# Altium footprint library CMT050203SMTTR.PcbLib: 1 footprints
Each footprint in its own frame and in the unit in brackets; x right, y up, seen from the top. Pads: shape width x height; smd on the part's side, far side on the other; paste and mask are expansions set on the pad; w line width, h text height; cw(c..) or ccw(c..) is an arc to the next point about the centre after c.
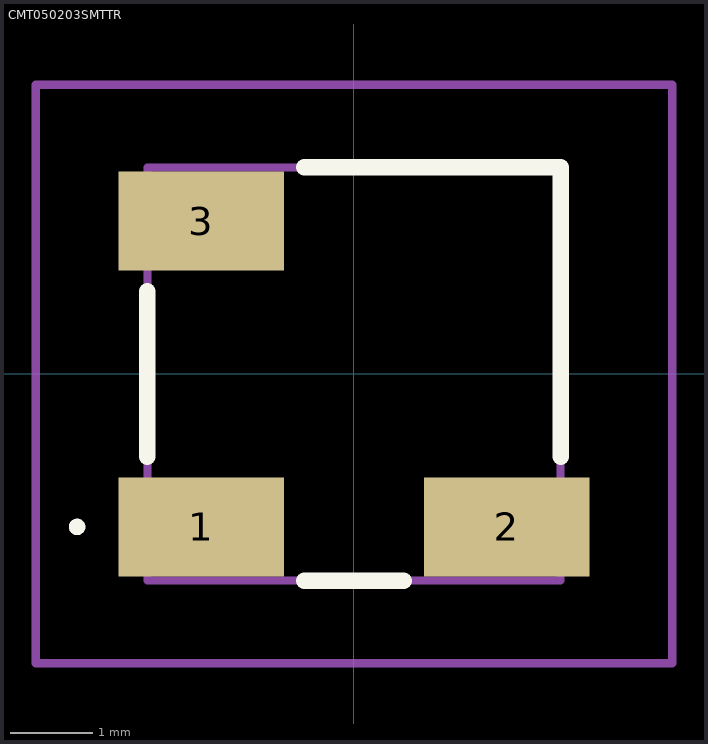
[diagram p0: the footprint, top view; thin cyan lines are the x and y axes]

## CMT050203SMTTR [mm]
pads (3):
  rect 2x1.2 smd: 1(-1.85,-1.85) 2(1.85,-1.85) 3(-1.85,1.85)
Top Overlay:
  lines w0.1: -3.4,-1.85 -3.4,-1.85 ; -3.4,-1.85 ccw(c-3.35,-1.85) -3.3,-1.85 ; -3.4,-1.85 cw(c-3.35,-1.85) -3.3,-1.85 ; -3.3,-1.85 -3.3,-1.85
  lines w0.2: -2.5,-1 -2.5,1 ; -0.6,-2.5 0.6,-2.5 ; -0.6,2.5 2.5,2.5 2.5,-1
Mechanical 15:
  lines w0.1: -2.5,-2.5 2.5,-2.5 2.5,2.5 -2.5,2.5 -2.5,-2.5
Mechanical 20:
  lines w0.1: -3.85,-3.5 3.85,-3.5 3.85,3.5 -3.85,3.5 -3.85,-3.5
